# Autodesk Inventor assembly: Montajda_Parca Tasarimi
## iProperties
Company: Autodesk, Inc.
Shininess: 64.0
Length Units: 11269
Angle Units: 11279
Time Units: 11290
Mass Units: 11283
Length Display Precision: 3
Angle Display Precision: 2
Compacted: True
Created: 2003-12
Part Number: Montajda_Parca Tasarimi
Document SubType Name: Assembly
Catalog Web Link: www.autodesk.com
Vendor: Autodesk, Inc.
Designer: Administrator
Manufacturer: Standard
Standards Organization: Custom
Density: 0.0
Volumn: 0.0
Area: 0.0
PropertySet Name: Model Information
Control State: 0
Master: False
Checked Out: False
Author: Administrator
